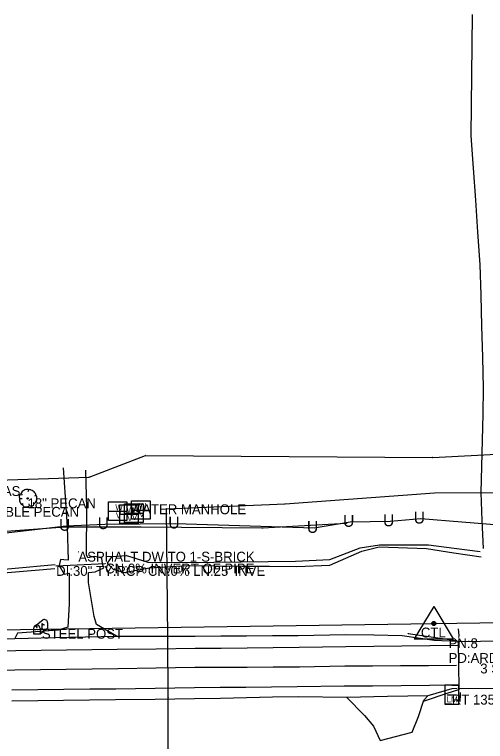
# Model space of a CAD drawing. Extents: x 1800653 to 1804042, y 522635 to 523313.
# Drawn here: x 1802007.6 to 1802246.9, y 522942.8 to 523311.8 of the extents above; entities that cross this region are included whole.
import ezdxf

# ---------------------------------------------------------------- set-up
doc = ezdxf.new("R2010")
doc.units = 0
for name, color, linetype in [('Default', 7, 'Continuous'), ('S_BASELINE', 7, 'Continuous'), ('S_BRIDGE', 7, 'Continuous'), ('S_DITCHLINE', 7, 'Continuous'), ('S_DRG_PT_SYM', 7, 'Continuous'), ('S_EDGE_PAVEMENT', 7, 'Continuous'), ('S_FIBER_OPTIC_CABLE', 7, 'Continuous'), ('S_GAS_UTILITIES', 7, 'Continuous'), ('S_GUARDRAIL', 7, 'Continuous'), ('S_LOG_MILE', 7, 'Continuous'), ('S_LOG_MILE_ANNOT', 7, 'Continuous'), ('S_MAILBOX', 7, 'Continuous'), ('S_MAILBOX_ANNOT', 7, 'Continuous'), ('S_MSC_PT_SYM', 7, 'Continuous'), ('S_PAVEMENT_CROWN', 7, 'Continuous'), ('S_PRIMARY_CTL', 7, 'Continuous'), ('S_PRIMARY_CTL_ANNOT', 7, 'Continuous'), ('S_RDW_PT_SYM', 7, 'Continuous'), ('S_SHOULDER', 7, 'Continuous'), ('S_SIDE_DRAIN', 7, 'Continuous'), ('S_SIDE_DRAIN_ANNOT', 7, 'Continuous'), ('S_STR_PT_SYM', 7, 'Continuous'), ('S_STREAM', 7, 'Continuous'), ('S_SURVEY_TEXT_ANNOT', 7, 'Continuous'), ('S_TREE', 7, 'Continuous'), ('S_TREE_ANNOT', 7, 'Continuous'), ('S_UNDERGROUND_CABLE', 7, 'Continuous'), ('S_UTILITY_POLE_ANNOT', 7, 'Continuous'), ('S_UTL_PT_SYM', 7, 'Continuous'), ('S_WALL', 7, 'Continuous'), ('S_WATER_UTILITIES', 7, 'Continuous')]:
    doc.layers.add(name, color=color, linetype=linetype)

msp = doc.modelspace()

# ---------------------------------------------------------------- linework, layer by layer
at = {"layer": 'S_BASELINE'}
for p, q in [((1802220.63, 523002.66), (1803097.96, 523013.6)), ((1801547.65, 522992.81), (1802220.63, 523002.66))]:
    msp.add_line(p, q, dxfattribs=at)
at = {"layer": 'S_BRIDGE'}
for p, q in [((1802280.74, 522994.16), (1802233.06, 522993.43)), ((1802233.06, 522993.43), (1802233.4, 522969.59)), ((1802233.4, 522969.59), (1802281.13, 522970.26))]:
    msp.add_line(p, q, dxfattribs=at)
at = {"layer": 'S_DITCHLINE'}
for points in [[(1802054.83, 523033.28), (1802057.17, 523036.68), (1802064.47, 523037.15), (1802075.38, 523033.77), (1802095.09, 523033.65), (1802108.9, 523033.83), (1802122.72, 523034), (1802136.54, 523034.17), (1802150.35, 523034.35), (1802167.78, 523035.21), (1802183.28, 523041.05), (1802192.96, 523042.62), (1802217.83, 523042.57), (1802230.99, 523040.86), (1802244.14, 523039.14)], [(1802054.75, 523033.29), (1802057.73, 523030.21), (1802063.28, 523028.61), (1802075.95, 523030.92), (1802095.28, 523032.05), (1802109.24, 523031.95), (1802123.19, 523031.84), (1802137.15, 523031.74), (1802151.11, 523031.64), (1802167.8, 523032.21), (1802184, 523039.39), (1802192.8, 523041.57), (1802216.93, 523040.68), (1802230.78, 523038.58), (1802244.62, 523036.47)], [(1801715.52, 523013.67), (1801737.96, 523013.82), (1801760.39, 523013.98), (1801774.8, 523014.45), (1801789.21, 523014.92), (1801803.63, 523015.39), (1801818.04, 523015.87), (1801833.05, 523016.17), (1801848.07, 523016.47), (1801863.08, 523016.78), (1801878.09, 523017.08), (1801891.54, 523017.92), (1801904.99, 523018.76), (1801918.43, 523019.6), (1801931.88, 523020.44), (1801948.3, 523023.92), (1801964.72, 523027.39), (1801983.79, 523028.48), (1802006.04, 523030.52), (1802028.29, 523032.57)], [(1801715.06, 523010.34), (1801737.8, 523011.35), (1801760.54, 523012.35), (1801774.86, 523012.86), (1801789.18, 523013.37), (1801803.51, 523013.87), (1801817.83, 523014.38), (1801832.83, 523014.54), (1801847.83, 523014.7), (1801862.83, 523014.86), (1801877.83, 523015.02), (1801891.38, 523015.98), (1801904.92, 523016.94), (1801918.47, 523017.9), (1801932.01, 523018.86), (1801948.49, 523022.35), (1801964.98, 523025.83), (1801983.86, 523026.84), (1802006.01, 523028.72), (1802028.15, 523030.6)]]:
    msp.add_lwpolyline(points, dxfattribs=at)
at = {"layer": 'S_DRG_PT_SYM'}
for points in [[(1802028.77, 523031.86), (1802028.77, 523031.9), (1802028.77, 523031.86), (1802028.72, 523031.86), (1802028.77, 523031.86), (1802028.77, 523031.8), (1802028.77, 523031.86), (1802028.82, 523031.86)], [(1802053.7, 523033.08), (1802053.7, 523033.13), (1802053.7, 523033.08), (1802053.65, 523033.08), (1802053.7, 523033.08), (1802053.7, 523033.03), (1802053.7, 523033.08), (1802053.75, 523033.08)]]:
    msp.add_lwpolyline(points, dxfattribs=at)
at = {"layer": 'S_EDGE_PAVEMENT'}
for points in [[(1802032.26, 523081.77), (1802033.29, 523066.75), (1802034.32, 523051.72), (1802034.87, 523034.84), (1802032.63, 523035.06), (1802031.05, 523035.18), (1802030.32, 523032.14), (1802032.76, 523027.71), (1802035.25, 523028.3), (1802035.43, 523028.26), (1802035.31, 523012.61), (1802034.78, 523000.74), (1802029.85, 522999.3), (1802009.1, 522997.83), (1802007.73, 522995.08)], [(1802059.51, 522996.23), (1802049.27, 523002.17), (1802048.11, 523006.14), (1802045.25, 523023.48), (1802045.14, 523028.48), (1802048.59, 523028.9), (1802052.94, 523030.88), (1802052.26, 523032.98), (1802052.05, 523035.81), (1802048.5, 523036.66), (1802044.81, 523036.03), (1802044.11, 523037.61), (1802044.38, 523061.02), (1802043.78, 523080.58)], [(1801985.96, 522988.74), (1802008.27, 522988.88), (1802021.16, 522989.07), (1802034.04, 522989.25), (1802046.92, 522989.44), (1802059.81, 522989.63), (1802079.63, 522989.87), (1802099.46, 522990.1), (1802112.65, 522990.23), (1802125.84, 522990.36), (1802139.03, 522990.49), (1802152.22, 522990.62), (1802175.86, 522991.03), (1802190.09, 522991.19), (1802204.33, 522991.36), (1802218.56, 522991.53), (1802232.8, 522991.7)], [(1802006.24, 522969.02), (1802019.45, 522969.16), (1802032.67, 522969.3), (1802045.88, 522969.44), (1802059.09, 522969.58), (1802079.11, 522969.85), (1802099.13, 522970.12), (1802112.16, 522970.27), (1802125.2, 522970.42), (1802138.24, 522970.58), (1802151.27, 522970.73), (1802175.06, 522970.95), (1802189.51, 522971.1), (1802203.97, 522971.26), (1802218.42, 522971.42), (1802232.88, 522971.57)], [(1802176.33, 522965.28), (1802185.45, 522956.04), (1802189.96, 522950.58), (1802193.28, 522943.31), (1802209.67, 522947.54), (1802212.85, 522955.53), (1802215.58, 522963.81), (1802217.69, 522966.06)]]:
    msp.add_lwpolyline(points, dxfattribs=at)
at = {"layer": 'S_FIBER_OPTIC_CABLE'}
for p, q in [((1802033.18, 523051.52), (1801996.45, 523048.92)), ((1802071.97, 523051.62), (1802033.18, 523051.52)), ((1802133.57, 523051.03), (1802071.97, 523051.62)), ((1802176.25, 523053.39), (1802133.57, 523051.03))]:
    msp.add_line(p, q, dxfattribs=at)
at = {"layer": 'S_GAS_UTILITIES'}
for p, q in [((1802045.49, 523076.91), (1802074.14, 523087.9)), ((1802074.14, 523087.9), (1802074.12, 523087.98)), ((1802074.12, 523087.98), (1802220.06, 523086.97)), ((1802220.06, 523086.97), (1802286.56, 523090.26)), ((1801909.53, 523072.41), (1802045.49, 523076.91))]:
    msp.add_line(p, q, dxfattribs=at)
at = {"layer": 'S_GUARDRAIL'}
for p, q in [((1802207.57, 522997.65), (1802231.94, 522994.1)), ((1802227.37, 522967.25), (1802233.26, 522969.09)), ((1802215.82, 522963.44), (1802227.37, 522967.25))]:
    msp.add_line(p, q, dxfattribs=at)
at = {"layer": 'S_LOG_MILE'}
for p, q in [((1802229.73, 522971.33), (1802233.33, 522971.33)), ((1802227.33, 522966.53), (1802232.13, 522966.53)), ((1802229.73, 522961.73), (1802226.13, 522961.73))]:
    msp.add_line(p, q, dxfattribs=at)
msp.add_lwpolyline([(1802233.33, 522971.33), (1802226.13, 522971.33), (1802226.13, 522961.73), (1802233.33, 522961.73)], close=True, dxfattribs=at)
at = {"layer": 'S_MAILBOX'}
for p, q in [((1802017.89, 523001.38), (1802022.03, 523004.49)), ((1802021.51, 523002.67), (1802021.51, 522999.95)), ((1802024.46, 523003.01), (1802024.46, 523000.3)), ((1802017.34, 523000.1), (1802017.34, 522997.39)), ((1802020.66, 522997.39), (1802024.46, 523000.3)), ((1802020.66, 523000.1), (1802020.66, 522997.39)), ((1802017.34, 522997.39), (1802020.66, 522997.39))]:
    msp.add_line(p, q, dxfattribs=at)
for points in [[(1802021.51, 523002.67), (1802022.62, 523002), (1802021.51, 523001.66)], [(1802018.52, 523001.22), (1802018.75, 523001.08), (1802018.75, 523000.69), (1802019.05, 523000.69), (1802019.05, 523001.05), (1802018.86, 523001.3), (1802018.52, 523001.25)]]:
    msp.add_lwpolyline(points, dxfattribs=at)
for centre, end in [((1802022.8, 523003.01), 117.5718), ((1802019, 523000.1), 180)]:
    msp.add_arc(centre, 1.66, 0, end, dxfattribs=at)
msp.add_ellipse((1802021.51, 522999.95), major_axis=(0.145, 0.132), ratio=0.564646, dxfattribs=at)
at = {"layer": 'S_MSC_PT_SYM'}
for points in [[(1802066.18, 523063.15), (1802066.18, 523063.2), (1802066.18, 523063.15), (1802066.13, 523063.15), (1802066.18, 523063.15), (1802066.18, 523063.1), (1802066.18, 523063.15), (1802066.23, 523063.15)], [(1802040.06, 523039.08), (1802040.06, 523039.13), (1802040.06, 523039.08), (1802040.01, 523039.08), (1802040.06, 523039.08), (1802040.06, 523039.03), (1802040.06, 523039.08), (1802040.11, 523039.08)], [(1802244.21, 522982.32), (1802244.21, 522982.37), (1802244.21, 522982.32), (1802244.16, 522982.32), (1802244.21, 522982.32), (1802244.21, 522982.27), (1802244.21, 522982.32), (1802244.26, 522982.32)]]:
    msp.add_lwpolyline(points, dxfattribs=at)
at = {"layer": 'S_PAVEMENT_CROWN'}
msp.add_lwpolyline([(1801985.65, 522978.78), (1802007.78, 522979.15), (1802020.86, 522979.32), (1802033.94, 522979.5), (1802047.02, 522979.67), (1802060.09, 522979.84), (1802079.63, 522980.13), (1802099.17, 522980.42), (1802112.47, 522980.5), (1802125.77, 522980.57), (1802139.07, 522980.65), (1802152.36, 522980.73), (1802175.33, 522981.11), (1802189.53, 522981.2), (1802203.73, 522981.28), (1802217.93, 522981.36), (1802232.12, 522981.45)], dxfattribs=at)
at = {"layer": 'S_PRIMARY_CTL'}
for p, q in [((1802220.63, 523011.36), (1802210.6, 522994.85)), ((1802220.63, 523011.36), (1802230.46, 522994.85)), ((1802210.6, 522994.85), (1802230.46, 522994.85))]:
    msp.add_line(p, q, dxfattribs=at)
for radius in [1.04, 0.609, 0.344]:
    msp.add_circle((1802220.63, 523002.66), radius, dxfattribs=at)
at = {"layer": 'S_RDW_PT_SYM'}
for points in [[(1802207.57, 522997.65), (1802207.57, 522997.7), (1802207.57, 522997.65), (1802207.52, 522997.65), (1802207.57, 522997.65), (1802207.57, 522997.6), (1802207.57, 522997.65), (1802207.62, 522997.65)], [(1802231.94, 522994.1), (1802231.94, 522994.15), (1802231.94, 522994.1), (1802231.89, 522994.1), (1802231.94, 522994.1), (1802231.94, 522994.05), (1802231.94, 522994.1), (1802231.99, 522994.1)], [(1802233.26, 522969.09), (1802233.26, 522969.14), (1802233.26, 522969.09), (1802233.21, 522969.09), (1802233.26, 522969.09), (1802233.26, 522969.04), (1802233.26, 522969.09), (1802233.31, 522969.09)], [(1802227.37, 522967.25), (1802227.37, 522967.3), (1802227.37, 522967.25), (1802227.32, 522967.25), (1802227.37, 522967.25), (1802227.37, 522967.2), (1802227.37, 522967.25), (1802227.42, 522967.25)], [(1802215.82, 522963.44), (1802215.82, 522963.49), (1802215.82, 522963.44), (1802215.77, 522963.44), (1802215.82, 522963.44), (1802215.82, 522963.39), (1802215.82, 522963.44), (1802215.87, 522963.44)]]:
    msp.add_lwpolyline(points, dxfattribs=at)
at = {"layer": 'S_SHOULDER'}
for points in [[(1801986.27, 522994.7), (1802007.75, 522995.08), (1802027.91, 522995.58), (1802043.63, 522995.9), (1802059.35, 522996.23), (1802079.33, 522996.25), (1802099.31, 522996.28), (1802112.42, 522996.36), (1802125.53, 522996.44), (1802138.64, 522996.51), (1802151.75, 522996.59), (1802175.78, 522997.17), (1802190.14, 522996.91), (1802204.5, 522996.64), (1802220.79, 522994.24), (1802232.61, 522993.73)], [(1802006.29, 522963.48), (1802019.43, 522963.62), (1802032.57, 522963.76), (1802045.72, 522963.9), (1802058.86, 522964.04), (1802078.99, 522964.31), (1802099.12, 522964.59), (1802112.3, 522964.84), (1802125.49, 522965.1), (1802138.68, 522965.36), (1802151.86, 522965.61), (1802176.35, 522965.29), (1802197.02, 522965.73), (1802217.7, 522966.16), (1802229.97, 522969.74), (1802232.51, 522969.79)]]:
    msp.add_lwpolyline(points, dxfattribs=at)
at = {"layer": 'S_SIDE_DRAIN'}
msp.add_line((1802028.77, 523031.86), (1802053.7, 523033.08), dxfattribs=at)
at = {"layer": 'S_STR_PT_SYM'}
for points in [[(1802233.06, 522993.43), (1802233.06, 522993.93), (1802233.06, 522993.43), (1802232.56, 522993.43), (1802233.06, 522993.43), (1802233.06, 522992.93), (1802233.06, 522993.43), (1802233.56, 522993.43)], [(1802233.4, 522969.59), (1802233.4, 522970.09), (1802233.4, 522969.59), (1802232.9, 522969.59), (1802233.4, 522969.59), (1802233.4, 522969.09), (1802233.4, 522969.59), (1802233.9, 522969.59)]]:
    msp.add_lwpolyline(points, dxfattribs=at)
at = {"layer": 'S_STREAM'}
msp.add_lwpolyline([(1802240.14, 523311.8), (1802239.95, 523296.4), (1802239.76, 523280.99), (1802239.57, 523265.58), (1802239.38, 523250.18), (1802240.55, 523233.87), (1802241.71, 523217.57), (1802242.88, 523201.27), (1802244.04, 523184.96), (1802244.47, 523169.28), (1802244.9, 523153.59), (1802245.33, 523137.9), (1802245.76, 523122.21), (1802245.43, 523108.95), (1802245.11, 523095.68), (1802244.78, 523082.42), (1802244.45, 523069.16), (1802245.04, 523054.95), (1802245.62, 523040.75)], dxfattribs=at)
at = {"layer": 'S_TREE'}
for p, q in [((1802011, 523068.42), (1802011.51, 523067.84)), ((1802014.8, 523070.43), (1802014.41, 523069.58)), ((1802010.34, 523066.09), (1802011.47, 523066.09)), ((1802018.37, 523067.64), (1802017.71, 523067.37)), ((1802011.51, 523062.92), (1802011.97, 523063.61)), ((1802015.19, 523062.64), (1802015.11, 523063.42)), ((1802017.59, 523063.54), (1802017.13, 523063.96))]:
    msp.add_line(p, q, dxfattribs=at)
msp.add_circle((1802014.24, 523066.19), 0.341, dxfattribs=at)
for centre, major_axis, ratio, start_param, end_param in [((1802012.91, 523069.39), (1.86, 1.08), 0.471018, 0, 3.141593), ((1802016.56, 523069.07), (-1.81, 1.36), 0.405113, 3.141593, 6.283186), ((1802010.67, 523067.27), (0.31, 1.03), 0.646762, 0, 3.141593), ((1802010.98, 523064.62), (-0.61, 1.6), 0.420543, 6.283185, 9.424777), ((1802017.92, 523065.66), (0.46, 2.04), 0.482994, 3.141593, 6.283185), ((1802013.44, 523062.84), (-1.83, 0.19), 0.529943, 0, 3.141593), ((1802016.4, 523063.14), (1.09, 0.46), 0.711534, 3.141592, 6.283185)]:
    msp.add_ellipse(centre, major_axis=major_axis, ratio=ratio, start_param=start_param, end_param=end_param, dxfattribs=at)
at = {"layer": 'S_UNDERGROUND_CABLE'}
for p, q in [((1802159.76, 523051.23), (1802178.1, 523054.31)), ((1802178.1, 523054.31), (1802198.41, 523054.56)), ((1802198.41, 523054.56), (1802213.99, 523055.95)), ((1802213.99, 523055.95), (1802292.61, 523049.61)), ((1801996.95, 523047.93), (1802033.83, 523052.3)), ((1802033.83, 523052.3), (1802053.47, 523053.13)), ((1802053.47, 523053.13), (1802089.35, 523053.45)), ((1802089.35, 523053.45), (1802159.76, 523051.23))]:
    msp.add_line(p, q, dxfattribs=at)
at = {"layer": 'S_UTL_PT_SYM'}
for points in [[(1802074.12, 523087.98), (1802074.12, 523088.03), (1802074.12, 523087.98), (1802074.07, 523087.98), (1802074.12, 523087.98), (1802074.12, 523087.93), (1802074.12, 523087.98), (1802074.17, 523087.98)], [(1802074.14, 523087.9), (1802074.14, 523087.95), (1802074.14, 523087.9), (1802074.09, 523087.9), (1802074.14, 523087.9), (1802074.14, 523087.85), (1802074.14, 523087.9), (1802074.19, 523087.9)], [(1802220.06, 523086.97), (1802220.06, 523087.02), (1802220.06, 523086.97), (1802220.01, 523086.97), (1802220.06, 523086.97), (1802220.06, 523086.92), (1802220.06, 523086.97), (1802220.11, 523086.97)], [(1802045.49, 523076.91), (1802045.49, 523076.96), (1802045.49, 523076.91), (1802045.44, 523076.91), (1802045.49, 523076.91), (1802045.49, 523076.86), (1802045.49, 523076.91), (1802045.54, 523076.91)], [(1802220.95, 523069), (1802220.95, 523069.05), (1802220.95, 523069), (1802220.9, 523069), (1802220.95, 523069), (1802220.95, 523068.95), (1802220.95, 523069), (1802221, 523069)], [(1802145.11, 523063.5), (1802145.11, 523063.55), (1802145.11, 523063.5), (1802145.06, 523063.5), (1802145.11, 523063.5), (1802145.11, 523063.45), (1802145.11, 523063.5), (1802145.16, 523063.5)], [(1802084.74, 523060.85), (1802084.74, 523060.9), (1802084.74, 523060.85), (1802084.69, 523060.85), (1802084.74, 523060.85), (1802084.74, 523060.8), (1802084.74, 523060.85), (1802084.79, 523060.85)], [(1802033.18, 523051.52), (1802033.18, 523051.57), (1802033.18, 523051.52), (1802033.13, 523051.52), (1802033.18, 523051.52), (1802033.18, 523051.47), (1802033.18, 523051.52), (1802033.23, 523051.52)], [(1802071.97, 523051.62), (1802071.97, 523051.67), (1802071.97, 523051.62), (1802071.92, 523051.62), (1802071.97, 523051.62), (1802071.97, 523051.57), (1802071.97, 523051.62), (1802072.02, 523051.62)], [(1802133.57, 523051.03), (1802133.57, 523051.08), (1802133.57, 523051.03), (1802133.52, 523051.03), (1802133.57, 523051.03), (1802133.57, 523050.98), (1802133.57, 523051.03), (1802133.62, 523051.03)], [(1802176.25, 523053.39), (1802176.25, 523053.44), (1802176.25, 523053.39), (1802176.2, 523053.39), (1802176.25, 523053.39), (1802176.25, 523053.34), (1802176.25, 523053.39), (1802176.3, 523053.39)], [(1802085.49, 522995.32), (1802085.49, 522995.37), (1802085.49, 522995.32), (1802085.44, 522995.32), (1802085.49, 522995.32), (1802085.49, 522995.27), (1802085.49, 522995.32), (1802085.54, 522995.32)], [(1802085.7, 522965.18), (1802085.7, 522965.23), (1802085.7, 522965.18), (1802085.65, 522965.18), (1802085.7, 522965.18), (1802085.7, 522965.13), (1802085.7, 522965.18), (1802085.75, 522965.18)]]:
    msp.add_lwpolyline(points, dxfattribs=at)
at = {"layer": 'S_WALL'}
for points in [[(1802233.37, 522995.63), (1802233.41, 522996.58), (1802233.16, 522999.96)], [(1802233.98, 522967.59), (1802233.93, 522966.65), (1802233.8, 522963.07)]]:
    msp.add_lwpolyline(points, dxfattribs=at)
at = {"layer": 'S_WATER_UTILITIES'}
for p, q in [((1802145.11, 523063.5), (1802220.95, 523069)), ((1802220.95, 523069), (1802292.52, 523069.23)), ((1802067.12, 523064.97), (1802076.54, 523064.97)), ((1802067.12, 523055.56), (1802067.12, 523064.97)), ((1802076.54, 523064.97), (1802076.54, 523055.56)), ((1802055.29, 523064.35), (1802064.71, 523064.35)), ((1802055.29, 523054.94), (1802055.29, 523064.35)), ((1802061.07, 523062.86), (1802070.48, 523062.86)), ((1802061.07, 523053.45), (1802061.07, 523062.86)), ((1802063.52, 523063.38), (1802072.93, 523063.38)), ((1802063.52, 523053.96), (1802063.52, 523063.38)), ((1802064.71, 523064.35), (1802064.71, 523054.94)), ((1802070.48, 523062.86), (1802070.48, 523053.45)), ((1802072.93, 523063.38), (1802072.93, 523053.96)), ((1802084.74, 523060.85), (1802145.11, 523063.5)), ((1802055.29, 523059.66), (1802064.71, 523059.66)), ((1802061.07, 523058.18), (1802070.48, 523058.18)), ((1802063.52, 523058.69), (1802072.93, 523058.69)), ((1802067.12, 523060.28), (1802076.54, 523060.28)), ((1802085.49, 522995.32), (1802084.74, 523060.85)), ((1802064.71, 523054.94), (1802055.29, 523054.94)), ((1802072.93, 523053.96), (1802063.52, 523053.96)), ((1802076.54, 523055.56), (1802067.12, 523055.56)), ((1802070.48, 523053.45), (1802061.07, 523053.45)), ((1802085.7, 522965.18), (1802085.49, 522995.32)), ((1802085.62, 522926.08), (1802085.7, 522965.18))]:
    msp.add_line(p, q, dxfattribs=at)

# ---------------------------------------------------------------- texts
at = {"layer": 'Default'}
for p in [(1802174.47, 523051.76), (1802194.78, 523052.01), (1802210.36, 523053.4), (1802030.2, 523049.75), (1802049.84, 523050.58), (1802085.72, 523050.9), (1802156.14, 523048.69)]:
    msp.add_text('U', height=6, dxfattribs=at).set_placement(p)
at = {"layer": 'S_LOG_MILE'}
msp.add_text('LM', height=3, dxfattribs=at).set_placement((1802227.19, 522962.69))
at = {"layer": 'S_LOG_MILE_ANNOT'}
msp.add_text('RT 135 SEC 2 LM 4.47', height=5, dxfattribs=at).set_placement((1802229.73, 522961.53))
at = {"layer": 'S_MAILBOX'}
msp.add_text('US', height=0.96, dxfattribs=at).set_placement((1802018.1, 522998.58))
at = {"layer": 'S_MAILBOX_ANNOT'}
msp.add_text('STEEL POST', height=5, dxfattribs=at).set_placement((1802021.51, 522994.95))
at = {"layer": 'S_PRIMARY_CTL'}
msp.add_text('CTL', height=5, dxfattribs=at).set_placement((1802214.05, 522995.59))
at = {"layer": 'S_PRIMARY_CTL_ANNOT'}
for s, p in [('PN:8', (1802228.13, 522990.16)), ('PD:ARDOT STD CAP STAMPED PN:8', (1802228.13, 522982.66))]:
    msp.add_text(s, height=5, dxfattribs=at).set_placement(p)
at = {"layer": 'S_SIDE_DRAIN_ANNOT'}
for s, p in [('DI:30" TY:RCP CN:0% LN:25\' INVE', (1802028.77, 523026.86)), ('CN:0% INVERT OF PIPE', (1802053.7, 523028.08))]:
    msp.add_text(s, height=5, dxfattribs=at).set_placement(p)
at = {"layer": 'S_SURVEY_TEXT_ANNOT'}
for s, p in [('WATER MANHOLE', (1802066.18, 523058.15)), ('ASPHALT DW TO 1-S-BRICK', (1802040.06, 523034.08)), ('3 SPAN CONC WOOD PIERS', (1802244.21, 522977.32))]:
    msp.add_text(s, height=5, dxfattribs=at).set_placement(p)
at = {"layer": 'S_TREE_ANNOT'}
for s, p in [('18" PECAN', (1802014.24, 523061.19)), ('15" DOUBLE PECAN', (1801976.35, 523056.86))]:
    msp.add_text(s, height=5, dxfattribs=at).set_placement(p)
at = {"layer": 'S_UTILITY_POLE_ANNOT'}
msp.add_text('TY:GASPIPELINE SOURCE GAS', height=5, dxfattribs=at).set_placement((1801909.55, 523067.41))
at = {"layer": 'S_WATER_UTILITIES'}
for s, p in [('W', (1802058.84, 523060.19)), ('W', (1802064.62, 523058.71)), ('W', (1802067.07, 523059.22)), ('W', (1802070.67, 523060.81)), ('V', (1802059.08, 523056.13)), ('V', (1802064.85, 523054.64)), ('V', (1802067.3, 523055.16)), ('V', (1802070.91, 523056.75))]:
    msp.add_text(s, height=3, dxfattribs=at).set_placement(p)

doc.saveas('drawing.dxf')
